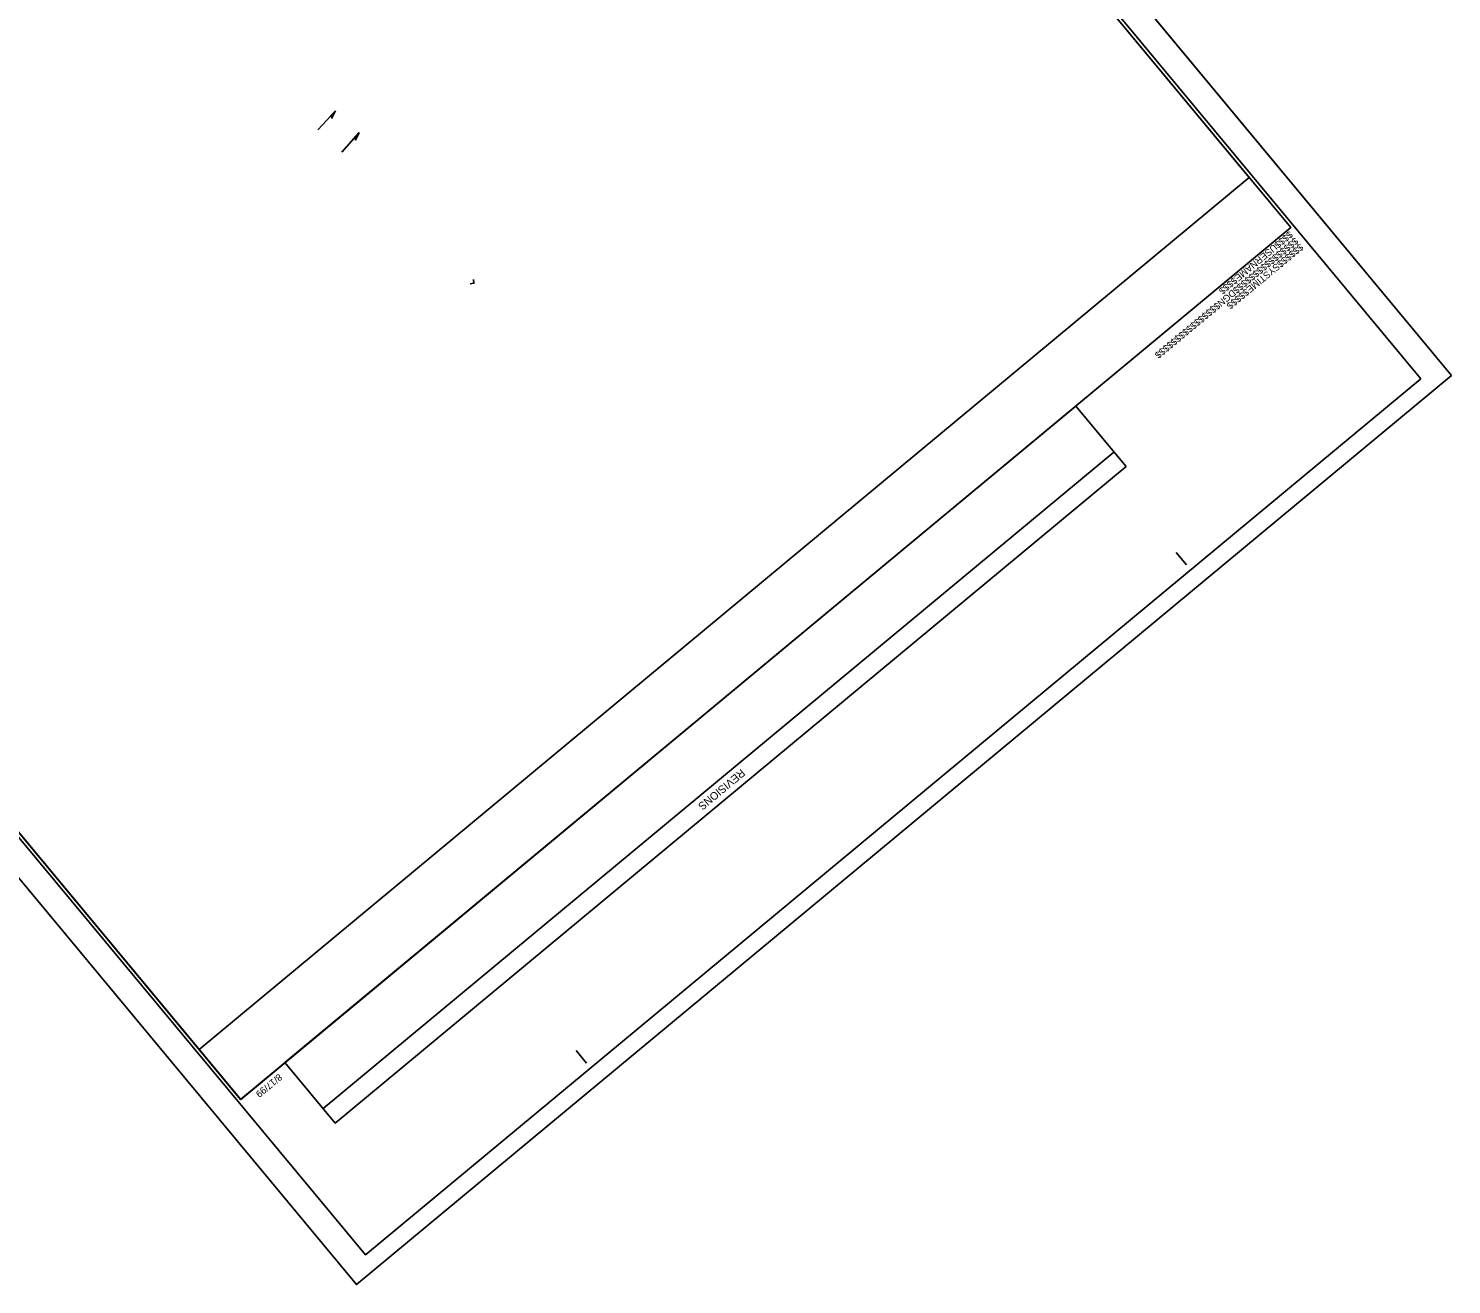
# Model space of a CAD drawing. Extents: x 2597036 to 2598995, y 852197 to 854192.
# Drawn here: x 2597901 to 2598995, y 852197 to 853163 of the extents above; entities that cross this region are included whole.
import ezdxf

# ---------------------------------------------------------------- set-up
doc = ezdxf.new("R2010")
doc.units = 0
for name, color, linetype in [('Default', 7, 'Continuous'), ('Prop Superelevation  Arrow CELL', 7, 'Continuous'), ('Prop Superelevation Label', 7, 'Continuous'), ('Sheet Block Revision CELL', 7, 'Continuous'), ('Sheet Clip Boundary CELL', 7, 'Continuous'), ('Sheet Cutting Line CELL', 7, 'Continuous'), ('Sheet Plan CELL', 7, 'Continuous'), ('Sheet Plan Layout CELL', 7, 'Continuous'), ('Sheet Plot Border Inside CELL', 7, 'Continuous'), ('Sheet Plot Border Outside CELL', 7, 'Continuous')]:
    doc.layers.add(name, color=color, linetype=linetype)

msp = doc.modelspace()

# ---------------------------------------------------------------- linework, layer by layer
at = {"layer": 'Default'}
msp.add_lwpolyline([(2598242.9, 852970.3), (2598243.3, 852967.3), (2598240.3, 852966.9)], dxfattribs=at)
at = {"layer": 'Prop Superelevation  Arrow CELL'}
for points in [[(2598136.8, 853099.9), (2598134, 853094.2), (2598133.5, 853096.6)], [(2598155, 853083.2), (2598152.2, 853077.5), (2598151.7, 853079.9)]]:
    msp.add_lwpolyline(points, close=True, dxfattribs=at)
at = {"layer": 'Prop Superelevation Label'}
for p, q in [((2598136.8, 853099.9), (2598123.1, 853085.3)), ((2598141.7, 853068.2), (2598155, 853083.2))]:
    msp.add_line(p, q, dxfattribs=at)
at = {"layer": 'Sheet Block Revision CELL'}
msp.add_line((2598735.6, 852837.4), (2598127.3, 852332.3), dxfattribs=at)
msp.add_lwpolyline([(2598744.9, 852826.2), (2598136.6, 852321.1), (2598097.9, 852367.7), (2598706.2, 852872.8)], close=True, dxfattribs=at)
at = {"layer": 'Sheet Clip Boundary CELL'}
msp.add_lwpolyline([(2598839.7, 853048.6), (2597945.3, 854125.7), (2597300.2, 853590), (2597421.1, 853444.4), (2597258.4, 853309.3), (2598031.9, 852377.8)], close=True, dxfattribs=at)
at = {"layer": 'Sheet Cutting Line CELL'}
for p, q in [((2598995.3, 852896.4), (2597919.8, 854191.6)), ((2597077.4, 853492.1), (2598152.9, 852196.9)), ((2598152.9, 852196.9), (2598995.3, 852896.4))]:
    msp.add_line(p, q, dxfattribs=at)
at = {"layer": 'Sheet Plan CELL'}
for p, q in [((2598871.6, 853010.1), (2598871.6, 853010.1)), ((2598791.5, 852750.6), (2598783.5, 852760.2)), ((2598329.9, 852367.3), (2598321.9, 852376.9)), ((2598063.8, 852339.3), (2598063.8, 852339.3))]:
    msp.add_line(p, q, dxfattribs=at)
for points in [[(2597105.5, 853493.4), (2598063.8, 852339.3), (2598871.6, 853010.1), (2597913.3, 854164.1)], [(2598871.6, 853010.1), (2598063.9, 852339.3), (2597233.3, 853339.4), (2597348.8, 853435.3), (2597221, 853589.2), (2597913.3, 854164.1)]]:
    msp.add_lwpolyline(points, close=True, dxfattribs=at)
at = {"layer": 'Sheet Plan Layout CELL'}
msp.add_lwpolyline([(2598063.9, 852339.3), (2598871.6, 853010.1), (2597913.3, 854164.1), (2597268.3, 853628.4), (2597421.1, 853444.4), (2597258.4, 853309.3)], close=True, dxfattribs=at)
at = {"layer": 'Sheet Plot Border Inside CELL'}
msp.add_lwpolyline([(2598971.6, 852893.7), (2597907.3, 854175.3), (2597095.6, 853501.4), (2598160, 852219.7)], close=True, dxfattribs=at)
at = {"layer": 'Sheet Plot Border Outside CELL'}
msp.add_lwpolyline([(2598995.3, 852896.4), (2597919.8, 854191.6), (2597077.4, 853492.1), (2598152.9, 852196.9)], close=True, dxfattribs=at)

# ---------------------------------------------------------------- texts
at = {"layer": 'Sheet Block Revision CELL'}
msp.add_text('REVISIONS', height=6, rotation=219.7067, dxfattribs=at).set_placement((2598448.8, 852594))
at = {"layer": 'Sheet Plan CELL'}
for s, p in [('$$$$$$$$$$$$$$$$DGN$$$$$$$$$$$$$$$$', (2598874.7, 853002.8)), ('$$$$USERNAME$$$$', (2598870.5, 853007.8)), ('$$$$$$SYSTIME$$$$$', (2598878.6, 852998.1)), ('8/17/99', (2598093, 852359.4))]:
    msp.add_text(s, height=5.25, rotation=219.7067, dxfattribs=at).set_placement(p)

doc.saveas('drawing.dxf')
